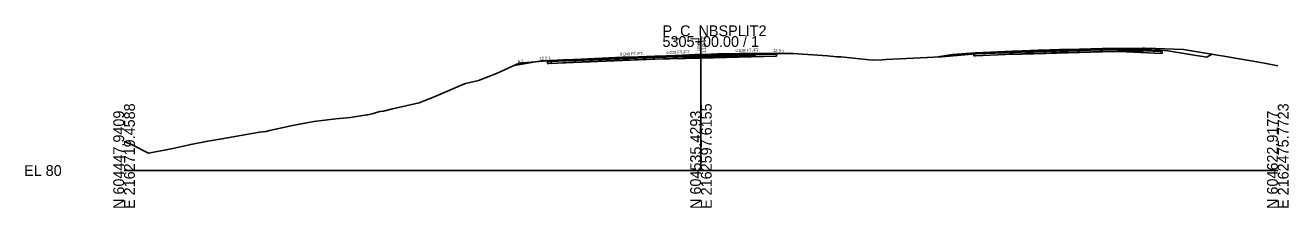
# Model space of a CAD drawing. Extents: x -26 to 1303, y -10 to 12038.
# Drawn here: x 974.3 to 1302.8, y 490.3 to 537.8 of the extents above; entities that cross this region are included whole.
import ezdxf

# ---------------------------------------------------------------- set-up
doc = ezdxf.new("R2010")
doc.units = 0
for name, color, linetype in [('RD_GPK_XS_Cell', 7, 'Continuous'), ('RD_XS_Base', 7, 'Continuous'), ('RD_XS_ExGround', 7, 'Continuous'), ('RD_XS_ExPaveRet', 7, 'Continuous'), ('RD_XS_Greenside', 7, 'Continuous'), ('RD_XS_Pave', 7, 'Continuous'), ('RD_XS_PaveOvlay_CP', 7, 'Continuous'), ('RD_XS_TieSlope', 7, 'Continuous'), ('RD_XS_TX_Elev_EX', 7, 'Continuous'), ('RD_XS_TX_Elev_PR', 7, 'Continuous'), ('RD_XS_TX_ShdSlope', 7, 'Continuous'), ('RD_XS_TX_Slope', 7, 'Continuous')]:
    doc.layers.add(name, color=color, linetype=linetype)

msp = doc.modelspace()

# ---------------------------------------------------------------- linework, layer by layer
at = {"layer": 'RD_GPK_XS_Cell'}
for p, q in [((1150, 500), (1150, 535)), ((1000, 500), (1150, 500)), ((1150, 500), (1300, 500))]:
    msp.add_line(p, q, dxfattribs=at)
at = {"layer": 'RD_XS_Base'}
for p, q in [((1138, 529.48), (1110.57, 528.38)), ((1110.57, 527.88), (1138, 528.98)), ((1150, 529.79), (1138, 529.48)), ((1138, 529.48), (1138, 529.48)), ((1138, 528.98), (1150, 529.29)), ((1138, 528.98), (1138, 528.98)), ((1150, 529.79), (1169.64, 530.3)), ((1150, 529.29), (1150, 529.95)), ((1150, 529.95), (1150, 529.95)), ((1150, 529.95), (1150, 529.95)), ((1150, 529.95), (1150, 529.79)), ((1169.64, 529.8), (1150, 529.29)), ((1150, 529.79), (1150, 529.79)), ((1150, 529.29), (1150, 529.79)), ((1150, 529.79), (1150, 529.79)), ((1150, 529.79), (1150, 529.79)), ((1150, 529.29), (1150, 529.29)), ((1169.14, 530.29), (1169.14, 530.29)), ((1169.64, 530.3), (1169.64, 529.8)), ((1169.64, 530.27), (1169.64, 530.27)), ((1221.31, 530.37), (1220.93, 530.35)), ((1220.93, 530.35), (1220.93, 530.24)), ((1220.93, 530.24), (1220.93, 529.85)), ((1220.93, 529.85), (1221.31, 529.87)), ((1221.43, 530.37), (1221.31, 530.37)), ((1221.31, 529.87), (1221.43, 529.87)), ((1229.07, 530.68), (1221.43, 530.37)), ((1221.43, 529.87), (1229.07, 530.18)), ((1233.43, 530.85), (1229.07, 530.68)), ((1229.07, 530.18), (1233.43, 530.35)), ((1239.56, 531.02), (1233.43, 530.85)), ((1233.43, 530.35), (1239.56, 530.52)), ((1245.43, 531.19), (1239.56, 531.02)), ((1239.56, 530.52), (1245.43, 530.69)), ((1254.43, 531.44), (1245.43, 531.19)), ((1245.43, 531.31), (1245.43, 531.35)), ((1245.43, 531.35), (1245.43, 531.19)), ((1245.43, 531.19), (1245.43, 531.31)), ((1245.43, 531.19), (1245.43, 531.19)), ((1245.43, 531.19), (1245.43, 530.69)), ((1245.43, 531.19), (1245.43, 531.19)), ((1245.43, 531.07), (1245.43, 531.19)), ((1245.43, 530.69), (1245.43, 531.07)), ((1245.43, 530.69), (1254.43, 530.94)), ((1257.43, 531.52), (1254.43, 531.44)), ((1254.43, 530.94), (1257.43, 531.02)), ((1260.45, 531.4), (1257.43, 531.52)), ((1257.43, 531.02), (1260.57, 530.9)), ((1269.43, 531.04), (1260.45, 531.4)), ((1260.57, 530.9), (1269.93, 530.52)), ((1269.56, 531.04), (1269.43, 531.04)), ((1269.93, 531.02), (1269.56, 531.04)), ((1269.93, 530.9), (1269.93, 531.02)), ((1269.93, 530.52), (1269.93, 530.9)), ((1110.57, 528.38), (1110.07, 528.36)), ((1110.07, 528.36), (1110.07, 528.36)), ((1110.07, 528.36), (1110.07, 527.86)), ((1110.07, 527.86), (1110.57, 527.88)), ((1110.57, 528.38), (1110.57, 528.38)), ((1110.57, 527.88), (1110.57, 527.88))]:
    msp.add_line(p, q, dxfattribs=at)
at = {"layer": 'RD_XS_ExGround'}
msp.add_lwpolyline([(1000, 507.6), (1001.94, 506.78), (1006.39, 504.49), (1008.6, 504.99), (1010.49, 505.35), (1012.7, 505.76), (1017.34, 506.79), (1021.8, 507.62), (1025.46, 508.25), (1035.21, 510.01), (1036.92, 510.19), (1037.84, 510.43), (1042.98, 511.53), (1043.34, 511.61), (1043.79, 511.69), (1049.31, 512.74), (1055.04, 513.49), (1058.9, 513.84), (1063.08, 514.48), (1063.3, 514.49), (1064.52, 514.74), (1066.48, 515.41), (1067.42, 515.45), (1069.78, 516.03), (1076.69, 517.66), (1081.04, 519.35), (1088.5, 522.54), (1088.65, 522.6), (1088.81, 522.65), (1092.13, 523.47), (1096.86, 525.31), (1102.72, 527.95), (1107.93, 528.38), (1111.03, 528.66), (1114.11, 528.8), (1117.07, 528.94), (1129.61, 529.5), (1130.46, 529.53), (1134.98, 529.65), (1145.26, 530.04), (1148.57, 530.18), (1152.64, 530.31), (1154.41, 530.36), (1159.92, 530.44), (1162.05, 530.5), (1163.99, 530.53), (1168.3, 530.5), (1174, 530.49), (1182.91, 529.84), (1185.37, 529.65), (1185.54, 529.65), (1185.6, 529.63), (1186.36, 529.57), (1194.65, 528.72), (1197.11, 528.8), (1198.13, 528.89), (1210.6, 529.5), (1212.62, 529.64), (1226.53, 530.79), (1230.47, 531.04), (1233.6, 531.16), (1237.71, 531.32), (1243.84, 531.5), (1244.3, 531.51), (1245.6, 531.52), (1246.35, 531.5), (1246.38, 531.5), (1246.45, 531.5), (1246.56, 531.51), (1255.28, 531.78), (1261.43, 531.82), (1265.27, 531.89), (1268.22, 531.78), (1270.59, 531.67), (1275.45, 531.5), (1283.25, 530.23), (1287.54, 529.5), (1288.9, 529.25), (1293.62, 528.48), (1297.44, 527.78), (1300, 527.23)], dxfattribs=at)
at = {"layer": 'RD_XS_ExPaveRet'}
for points in [[(1162.05, 530.5), (1159.92, 530.44), (1159.92, 530.44), (1154.41, 530.36), (1154.41, 530.36), (1152.64, 530.31), (1152.64, 530.31), (1148.57, 530.18), (1148.57, 530.18), (1148.57, 530.18), (1145.26, 530.04), (1145.26, 530.04), (1134.98, 529.65), (1130.46, 529.53), (1130.46, 529.53), (1130.46, 529.53), (1129.61, 529.5), (1117.07, 528.94), (1117.07, 528.94), (1114.11, 528.8), (1111.03, 528.66), (1111.03, 528.66), (1111.03, 528.66), (1111.03, 527.91), (1111.03, 527.91), (1114.11, 528.05), (1117.07, 528.19), (1117.07, 528.19), (1129.61, 528.75), (1130.46, 528.78), (1130.46, 528.78), (1130.46, 528.78), (1134.98, 528.9), (1145.26, 529.29), (1145.26, 529.29), (1148.57, 529.43), (1148.57, 529.43), (1148.57, 529.43), (1152.64, 529.56), (1152.64, 529.56), (1154.41, 529.61), (1154.41, 529.61), (1159.92, 529.69), (1159.92, 529.69), (1162.05, 529.75), (1162.05, 529.75), (1163.98, 529.78), (1163.98, 530.53), (1163.98, 530.53), (1162.05, 530.5), (1162.05, 530.5)], [(1162.05, 530.5), (1159.92, 530.44), (1154.41, 530.36), (1152.64, 530.31), (1148.57, 530.18), (1145.26, 530.04), (1134.98, 529.65), (1130.46, 529.53), (1129.61, 529.5), (1117.07, 528.94), (1114.11, 528.8), (1111.03, 528.66), (1111.03, 528.66), (1111.03, 527.91), (1111.03, 527.91), (1114.11, 528.05), (1117.07, 528.19), (1129.61, 528.75), (1130.46, 528.78), (1134.98, 528.9), (1145.26, 529.29), (1148.57, 529.43), (1152.64, 529.56), (1154.41, 529.61), (1159.92, 529.69), (1162.05, 529.75), (1163.98, 529.78), (1163.98, 530.53), (1162.05, 530.5)], [(1261.43, 531.82), (1258.29, 531.8), (1255.28, 531.78), (1253.84, 531.73), (1249.43, 531.59), (1248.52, 531.55), (1247.86, 531.54), (1246.43, 531.51), (1246.24, 531.5), (1245.8, 531.52), (1245.6, 531.52), (1245.22, 531.52), (1244.47, 531.51), (1244.2, 531.5), (1243.21, 531.49), (1241.24, 531.43), (1239.21, 531.36), (1235.85, 531.23), (1234.34, 531.19), (1233.6, 531.16), (1231.04, 531.06), (1230.47, 531.04), (1230.47, 531.04), (1230.47, 531.04), (1230.47, 530.57), (1230.47, 530.29), (1230.47, 530.29), (1230.47, 530.29), (1231.04, 530.31), (1233.6, 530.41), (1234.34, 530.44), (1235.85, 530.48), (1239.21, 530.61), (1241.24, 530.68), (1243.21, 530.74), (1244.2, 530.75), (1244.47, 530.76), (1245.22, 530.77), (1245.6, 530.77), (1245.8, 530.77), (1246.24, 530.75), (1246.43, 530.76), (1247.86, 530.79), (1248.52, 530.8), (1249.43, 530.84), (1253.84, 530.98), (1255.28, 531.03), (1258.29, 531.05), (1261.43, 531.07), (1264.86, 531.13), (1265.27, 531.14), (1265.27, 531.4), (1265.27, 531.89), (1264.86, 531.88), (1261.43, 531.82)], [(1261.43, 531.82), (1258.29, 531.8), (1255.28, 531.78), (1253.84, 531.73), (1249.43, 531.59), (1248.52, 531.55), (1247.86, 531.54), (1246.43, 531.51), (1246.24, 531.5), (1245.8, 531.52), (1245.6, 531.52), (1245.22, 531.52), (1244.47, 531.51), (1244.2, 531.5), (1243.21, 531.49), (1241.24, 531.43), (1239.21, 531.36), (1235.85, 531.23), (1234.34, 531.19), (1233.6, 531.16), (1231.04, 531.06), (1230.47, 531.04), (1230.47, 531.04), (1230.47, 531.04), (1230.47, 530.57), (1230.47, 530.29), (1230.47, 530.29), (1230.47, 530.29), (1231.04, 530.31), (1233.6, 530.41), (1234.34, 530.44), (1235.85, 530.48), (1239.21, 530.61), (1241.24, 530.68), (1243.21, 530.74), (1244.2, 530.75), (1244.47, 530.76), (1245.22, 530.77), (1245.6, 530.77), (1245.8, 530.77), (1246.24, 530.75), (1246.43, 530.76), (1247.86, 530.79), (1248.52, 530.8), (1249.43, 530.84), (1253.84, 530.98), (1255.28, 531.03), (1258.29, 531.05), (1261.43, 531.07), (1264.86, 531.13), (1265.27, 531.14), (1265.27, 531.4), (1265.27, 531.89), (1264.86, 531.88), (1261.43, 531.82)]]:
    msp.add_lwpolyline(points, dxfattribs=at)
at = {"layer": 'RD_XS_Greenside'}
for p, q in [((1215.43, 530.21), (1211.58, 529.57)), ((1271.43, 531.2), (1281.43, 529.54)), ((1281.43, 529.54), (1282.93, 530.28)), ((1108.57, 528.54), (1101.36, 527.34))]:
    msp.add_line(p, q, dxfattribs=at)
at = {"layer": 'RD_XS_Pave'}
for p, q in [((1138, 529.8), (1110.57, 528.7)), ((1110.57, 528.54), (1138, 529.64)), ((1138, 529.64), (1110.57, 528.54)), ((1110.57, 528.38), (1138, 529.48)), ((1150, 530.11), (1138, 529.8)), ((1138, 529.64), (1150, 529.95)), ((1150, 529.95), (1138, 529.64)), ((1138, 529.8), (1138, 529.8)), ((1138, 529.48), (1150, 529.79)), ((1138, 529.64), (1138, 529.64)), ((1138, 529.64), (1138, 529.64)), ((1138, 529.48), (1138, 529.48)), ((1169.14, 530.61), (1150, 530.11)), ((1169.14, 530.45), (1150, 529.95)), ((1150, 529.95), (1169.14, 530.45)), ((1150, 529.79), (1169.14, 530.29)), ((1150, 530.11), (1150, 530.11)), ((1150, 529.95), (1150, 529.95)), ((1150, 529.95), (1150, 529.95)), ((1150, 529.95), (1150, 529.79)), ((1150, 529.95), (1150, 529.95)), ((1150, 529.79), (1150, 529.95)), ((1150, 529.95), (1150, 529.95)), ((1150, 529.95), (1150, 529.95)), ((1150, 529.79), (1150, 529.79)), ((1150, 529.79), (1150, 529.79)), ((1169.14, 530.45), (1169.14, 530.61)), ((1169.14, 530.61), (1169.14, 530.61)), ((1169.14, 530.29), (1169.14, 530.45)), ((1169.14, 530.45), (1169.14, 530.45)), ((1229.07, 531), (1221.43, 530.69)), ((1229.07, 530.84), (1221.43, 530.53)), ((1221.43, 530.53), (1229.07, 530.84)), ((1221.43, 530.69), (1221.43, 530.65)), ((1221.43, 530.37), (1229.07, 530.68)), ((1221.43, 530.65), (1221.43, 530.53)), ((1221.43, 530.53), (1221.43, 530.49)), ((1221.43, 530.49), (1221.43, 530.37)), ((1233.43, 531.17), (1229.07, 531)), ((1233.43, 531.01), (1229.07, 530.84)), ((1229.07, 530.84), (1233.43, 531.01)), ((1229.07, 530.68), (1233.43, 530.85)), ((1239.56, 531.34), (1233.43, 531.17)), ((1239.56, 531.18), (1233.43, 531.01)), ((1233.43, 531.01), (1239.56, 531.18)), ((1233.43, 530.85), (1239.56, 531.02)), ((1245.43, 531.51), (1239.56, 531.34)), ((1245.43, 531.35), (1239.56, 531.18)), ((1239.56, 531.18), (1245.43, 531.35)), ((1239.56, 531.02), (1245.43, 531.19)), ((1254.43, 531.76), (1245.43, 531.51)), ((1254.43, 531.6), (1245.43, 531.35)), ((1245.43, 531.35), (1254.43, 531.6)), ((1245.43, 531.19), (1254.43, 531.44)), ((1245.43, 531.31), (1245.43, 531.35)), ((1245.43, 531.35), (1245.43, 531.35)), ((1245.43, 531.35), (1245.43, 531.35)), ((1245.43, 531.35), (1245.43, 531.31)), ((1245.43, 531.19), (1245.43, 531.31)), ((1245.43, 531.31), (1245.43, 531.19)), ((1245.43, 531.19), (1245.43, 531.19)), ((1245.43, 531.19), (1245.43, 531.19)), ((1257.43, 531.84), (1254.43, 531.76)), ((1257.43, 531.68), (1254.43, 531.6)), ((1254.43, 531.6), (1257.43, 531.68)), ((1254.43, 531.44), (1257.43, 531.52)), ((1260.45, 531.72), (1257.43, 531.84)), ((1260.45, 531.56), (1257.43, 531.68)), ((1257.43, 531.68), (1260.45, 531.56)), ((1257.43, 531.52), (1260.45, 531.4)), ((1269.43, 531.36), (1260.45, 531.72)), ((1269.43, 531.2), (1260.45, 531.56)), ((1260.45, 531.56), (1269.43, 531.2)), ((1260.45, 531.4), (1269.43, 531.04)), ((1269.43, 531.32), (1269.43, 531.36)), ((1269.43, 531.2), (1269.43, 531.32)), ((1269.43, 531.16), (1269.43, 531.2)), ((1269.43, 531.04), (1269.43, 531.16)), ((1110.57, 528.7), (1110.57, 528.7)), ((1110.57, 528.7), (1110.57, 528.54)), ((1110.57, 528.54), (1110.57, 528.54)), ((1110.57, 528.54), (1110.57, 528.38))]:
    msp.add_line(p, q, dxfattribs=at)
at = {"layer": 'RD_XS_PaveOvlay_CP'}
for p, q in [((1138, 529.8), (1110.57, 528.7)), ((1150, 530.11), (1138, 529.8)), ((1138, 529.8), (1138, 529.8)), ((1169.14, 530.61), (1150, 530.11)), ((1150, 530.11), (1150, 530.11)), ((1229.07, 531), (1221.43, 530.69)), ((1233.43, 531.17), (1229.07, 531)), ((1239.56, 531.34), (1233.43, 531.17)), ((1245.43, 531.51), (1239.56, 531.34)), ((1254.43, 531.76), (1245.43, 531.51)), ((1257.43, 531.84), (1254.43, 531.76)), ((1260.45, 531.72), (1257.43, 531.84)), ((1269.43, 531.36), (1260.45, 531.72))]:
    msp.add_line(p, q, dxfattribs=at)
at = {"layer": 'RD_XS_TieSlope'}
for p, q in [((1169.14, 530.61), (1170.53, 530.5)), ((1221.43, 530.69), (1215.43, 530.21)), ((1269.43, 531.36), (1271.43, 531.2)), ((1110.57, 528.7), (1108.57, 528.54))]:
    msp.add_line(p, q, dxfattribs=at)

# ---------------------------------------------------------------- texts
at = {"layer": 'RD_GPK_XS_Cell'}
for s, p in [('P_C_NBSPLIT2', (1140, 535)), ('5305+00.00 / 1', (1140, 532.2)), ('EL 80', (974, 498.6))]:
    msp.add_text(s, height=2.8, dxfattribs=at).set_placement(p)
for s, p in [('E 2162719.4588', (1002.8, 490)), ('E 2162597.6155', (1152.8, 490)), ('E 2162475.7723', (1302.8, 490)), ('N 604447.9409', (1000, 490)), ('N 604535.4293', (1150, 490)), ('N 604622.9177', (1300, 490))]:
    msp.add_text(s, height=2.8, rotation=90, dxfattribs=at).set_placement(p)
at = {"layer": 'RD_XS_TX_Elev_EX'}
msp.add_text('110.23', height=0.6, rotation=90, dxfattribs=at).set_placement((1149.66, 531.05))
at = {"layer": 'RD_XS_TX_Elev_PR'}
msp.add_text('110.11', height=1, rotation=90, dxfattribs=at).set_placement((1151.32, 530.69))
at = {"layer": 'RD_XS_TX_ShdSlope'}
for rotation, p in [(4.5739, (1108.05, 528.82)), (355.4261, (1168.73, 530.96))]:
    msp.add_text('12.5:1', height=0.75, rotation=rotation, dxfattribs=at).set_placement(p)
at = {"layer": 'RD_XS_TX_Slope'}
for s, rotation, p in [('6:1', 9.4642, (1102.47, 528.01)), ('0.040 FT./FT.', 2.2906, (1128.99, 529.9)), ('0.028 FT./FT.', 1.6039, (1141, 530.35)), ('0.028 FT./FT.', 1.6039, (1159, 530.85))]:
    msp.add_text(s, height=0.75, rotation=rotation, dxfattribs=at).set_placement(p)

doc.saveas('drawing.dxf')
